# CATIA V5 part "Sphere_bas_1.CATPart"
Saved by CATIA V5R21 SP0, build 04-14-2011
Part number: Sphere_bas_gauche
Bounding box of the stored display mesh (mm): x -13.5 to 4, y -23 to 23, z -16.25 to 0
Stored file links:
  D:\FRANCE\Stage\CAO\CAO final\3D impression\Sphere_bas_1.CATPart
  D:\FRANCE\Stage\CAO\CAO final\3D impression\Sphere_assemblage.CATProduct
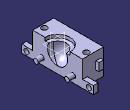
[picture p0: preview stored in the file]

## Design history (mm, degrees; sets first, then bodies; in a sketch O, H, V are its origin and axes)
External parameters (linked from other documents)
  External.Radius = 6 mm
  External.Length = 5.25 mm
Body1 (main body)
  Sketch1 on xy-plane, origin (0, 0, 0), H (1, 0, 0), V (0, 1, 0)
    line L1 (13.5, 16) -> (13.5, -16)
    line L2 (13.5, -16) -> (-13.5, -16)
    line L3 (-13.5, -16) -> (-13.5, 16)
    line L4 (-13.5, 16) -> (13.5, 16)
    length L1 = 32
    length L4 = 27
    vertical: L1 V, L3 V
    horizontal: L2 H, L4 H
    equidistance: L1 L3 O, L2 L4 O
  Pad1: profile Sketch1, direction (0, 0, -1), length 16.25 {= External.Radius +External.Length +5mm}
  Sketch2 on yz-plane, origin (0, 0, 0), H (0, 1, 0), V (0, 0, 1)
    arc A1 centre (0, -5.25) radius 6.5 from (0, -11.75) to (3.8324, 0) ccw
    point P1 (0, -5.25)
    line L1 (0, 0) -> (0, -11.75)
    point P3 (3.8324, 0)
    line L2 (3.8324, 0) -> (0, 0)
    radius A1 = 6.5 {= External.Radius +0.5mm}
    distance P1 H = 5.25 {= External.Length}
    vertical: L1 V
    horizontal: L2 H
    coincidence: V P1, L1 V, P3 H, L2 H
  Groove1: profile Sketch2, axis Sketch2.L1, angle 360
  Split1: SplitPlane yz-plane
  Sketch3 on face of Split1, origin (0, 0, 0), H (0, 1, 0), V (0, 0, 1)
    circle A1 centre (10, -12.25) radius 1.5
    point P1 (10, -12.25)
    reference projected line E1 (16, -16.25) -> (-16, -16.25) from edge [face of Split1 | end face of Pad1]
    reference projected line E2 (16, -16.25) -> (16, 0) from edge [face of Pad1 from Sketch1.L4 | face of Split1]
    circle A2 centre (-10, -12.25) radius 1.5
    radius A1 = 1.5
    distance P1 E1 = 4
    distance P1 E2 = 6
    symmetry: A1 A2 V
  Pad2: profile Sketch3, direction (1, 0, 0), length 4
  Sketch4 on start face of Pad1, origin (-3.898, -19.435, 0), H (1, 0, 0), V (0, 1, 0)
    point P1 (-1.102, 5.935)
    reference projected line E1 (3.898, 15.6026) -> (3.898, 3.435) from edge [start face of Pad1 | face of Split1]
    reference projected line E3 (-9.602, 3.435) -> (17.398, 3.435) from edge [face of Pad1 from Sketch1.L2 | start face of Pad1]
    distance P1 E1 = 5
    distance P1 E3 = 2.5
  Hole1: placed by Sketch4, at (-5, -13.5, 0) direction (0, 0, -1), diameter 3.5, depth 5
  Mirror1: of Hole1, about zx-plane
  Sketch5 on face of Pad1 from Sketch1.L2, origin (0, -16, 0), H (1, 0, 0), V (0, 0, 1)
    point P1 (0, -16.25)
    line L1 (0, -16.25) -> (0, -11.25)
    line L2 (0, -11.25) -> (-3, -11.25)
    line L3 (-3, -11.25) -> (-3, -16.25)
    line L4 (-3, -16.25) -> (0, -16.25)
    reference projected line E1 (-13.5, -16.25) -> (13.5, -16.25) from edge [end face of Pad1 | face of Pad1 from Sketch1.L2]
    length L3 = 5
    length L2 = 3
    coincidence: P1 V, L4 E1, L1 V
    vertical: L1 V, L3 V
    horizontal: L2 H, L4 H
  Pad3: profile Sketch5, direction (0, -1, 0), length 7
  Mirror2: of Pad3, about zx-plane
  Sketch6 on face of Mirror2, origin (0, -25.1327, -7.5812), H (0, 1, 0), V (0, 0, 1)
    point P1 (5.1327, -6.1688)
    reference projected line E1 (41.1327, -8.6688) -> (9.1327, -8.6688) from edge [face of Mirror2 | face of Mirror2]
    reference projected line E2 (2.1327, -8.6688) -> (2.1327, -3.6688) from edge [face of Mirror2 | end face of Pad3]
    distance P1 E1 = 2.5
    distance P1 E2 = 3
  Hole2: placed by Sketch6, at (0, -20, -13.75) direction (-1, 0, 0), diameter 3.2, through (limit type 3)
  Mirror3: of Hole2, about zx-plane
  Sketch7 on face of Pad1 from Sketch1.L4, origin (0, 16, 0), H (-1, 0, 0), V (0, 0, 1)
    point P1 (10, -7.75)
    line L1 (11.5, -5.25) -> (11.5, -10.25)
    line L2 (11.5, -10.25) -> (8.5, -10.25)
    line L3 (8.5, -10.25) -> (8.5, -5.25)
    line L4 (8.5, -5.25) -> (11.5, -5.25)
    reference projected line E1 (-13.5, -16.25) -> (13.5, -16.25) from edge [face of Mirror2 | face of Pad1 from Sketch1.L4]
    length L1 = 5
    length L2 = 3
    distance P1 E1 = 8.5
    distance P1 V = 10
    vertical: L1 V, L3 V
    horizontal: L2 H, L4 H
    equidistance: L1 L3 P1, L2 L4 P1
  Pad4: profile Sketch7, direction (0, 1, 0), length 2
  Mirror4: of Pad4, about zx-plane
  Sketch8 on start face of Pad1, origin (0, 0, 0), H (1, 0, 0), V (0, 1, 0)
    arc A1 centre (0, 0) radius 8 from (0, 8) to (0, -8) ccw
    point P1 (0, 8)
    line L1 (0, 8) -> (0, -8)
    radius A1 = 8
    coincidence: P1 V
    vertical: L1 V
  Pocket1: profile Sketch8, direction (0, 0, -1), length 2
